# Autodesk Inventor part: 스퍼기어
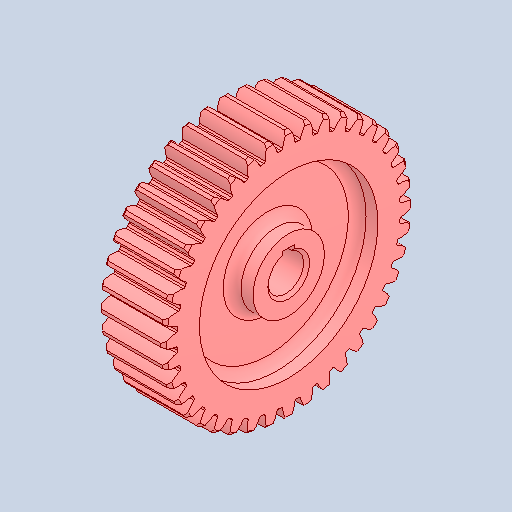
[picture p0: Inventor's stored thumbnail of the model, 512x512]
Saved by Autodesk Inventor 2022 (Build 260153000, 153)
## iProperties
Created: 2024-11
Part Number: 스퍼기어
Material: 강철, 탄소
Document SubType Name: Modeling
Designer: PC-12
Density: 7.85 g/cm^3
Appearance: 기본값
Author: jhkim
Sending System: Autodesk Inventor 2025
Preprocessor: ST-DEVELOPER v20
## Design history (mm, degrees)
node "스퍼기어1"
node "솔리드2"
node "솔리드1"
